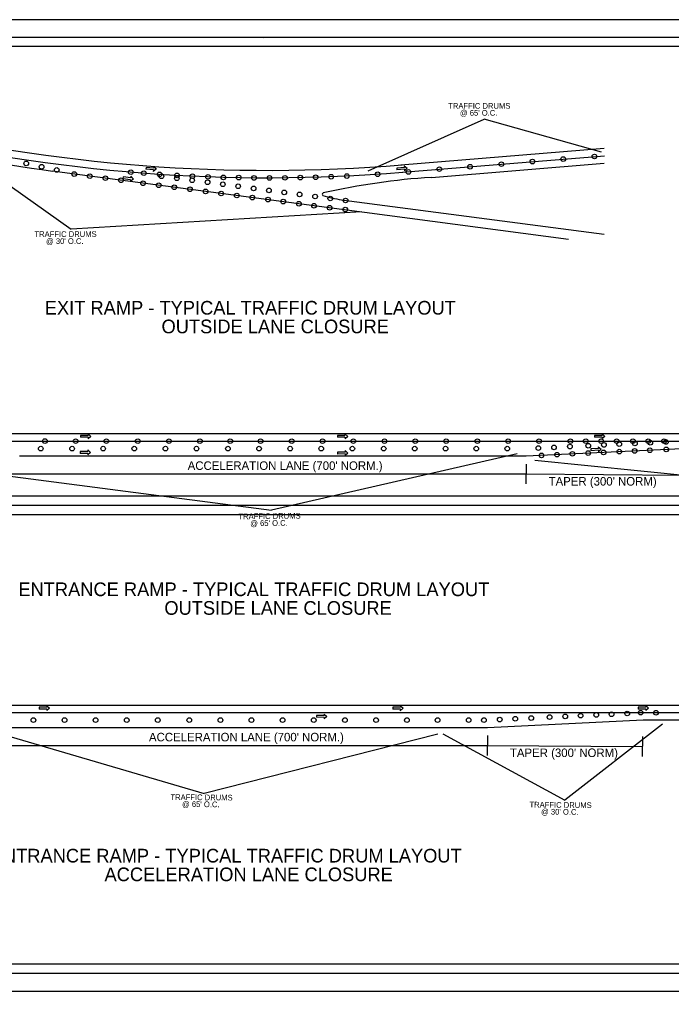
# Model space of a CAD drawing. Extents: x -500 to 213, y 382723 to 382830.
# Drawn here: x -79.9 to -8.3, y 382723.1 to 382829.8 of the extents above; entities that cross this region are included whole.
import ezdxf

# ---------------------------------------------------------------- set-up
doc = ezdxf.new("R2010")
doc.units = 0
for name, color, linetype in [('Default', 7, 'Continuous'), ('R_Border', 7, 'Continuous'), ('R_Border Plan-Plan', 7, 'Continuous'), ('R_MOT', 7, 'Continuous'), ('R_No Plot', 7, 'Continuous')]:
    doc.layers.add(name, color=color, linetype=linetype)

# ---------------------------------------------------------------- blocks, each defined once
blk = doc.blocks.new('DOT')
at = {"layer": 'Default'}
blk.add_circle((-0.4, -0.3), 3.75, dxfattribs=at)
blk = doc.blocks.new('SARROW')
at = {"layer": 'Default'}
for p, q in [((15.6, 3.2), (-13.8, 3.2)), ((-13.8, 3.2), (-13.8, -2.8)), ((15.6, 8.2), (15.6, 3.2)), ((15.6, 8.2), (26, 0.2)), ((26, 0.2), (15.6, -7.8)), ((15.6, -2.8), (-13.8, -2.8)), ((15.6, -2.8), (15.6, -7.8))]:
    blk.add_line(p, q, dxfattribs=at)

msp = doc.modelspace()

# ---------------------------------------------------------------- linework, layer by layer
at = {"layer": 'Default'}
for p, q in [((-38.04, 382813.83), (-15.74, 382815.66)), ((-37.87, 382813.03), (-15.7, 382814.84)), ((-76.32, 382813.17), (-19.64, 382805.7)), ((-34.7, 382812.47), (-15.74, 382814.02)), ((-44.58, 382810.02), (-15.74, 382806.22)), ((-97.81, 382784.35), (6.37, 382784.35)), ((-97.83, 382783.53), (6.35, 382783.53)), ((-24.28, 382781.9), (-7.21, 382782.72)), ((-79.93, 382781.9), (-24.28, 382781.9)), ((-24.29, 382781.01), (-24.34, 382778.83)), ((-89.24, 382779.92), (-24.32, 382779.92)), ((-107.24, 382754.56), (2.89, 382754.56)), ((-107.26, 382753.75), (2.87, 382753.75)), ((-28.53, 382752.11), (-11.45, 382752.93)), ((-11.45, 382752.93), (2.85, 382752.93)), ((-84.18, 382752.11), (-28.53, 382752.11)), ((-28.54, 382751.22), (-28.59, 382749.04)), ((-93.49, 382750.13), (-28.56, 382750.13)), ((-11.51, 382751.1), (-11.57, 382748.92))]:
    msp.add_line(p, q, dxfattribs=at)
for centre, major_axis, start_param, end_param in [((-52.59, 383072.52), (0, 260.09), 2.945637, 3.209664), ((-52.59, 383072.52), (0, 259.28), 2.945637, 3.209664), ((-52.59, 383072.52), (0, 260.91), 2.94688, 3.032274), ((-29.96, 382704.91), (0, 107.71), 0.052832, 0.186328), ((-46.57, 382810.62), (0, 0.136), 0.197268, 2.831699), ((-43.23, 382824.76), (0, -14.83), 6.00653, 6.174382)]:
    msp.add_ellipse(centre, major_axis=major_axis, ratio=0.833333, start_param=start_param, end_param=end_param, dxfattribs=at)
at = {"layer": 'R_Border'}
for p, q in [((-129.35, 382827.85), (28.74, 382827.85)), ((-53.09, 382827.72), (-53.09, 382827.72)), ((-53.09, 382827.72), (-53.09, 382827.72)), ((28.74, 382725.12), (-129.35, 382725.12))]:
    msp.add_line(p, q, dxfattribs=at)
at = {"layer": 'R_Border Plan-Plan'}
msp.add_line((-129.35, 382776.49), (28.74, 382776.49), dxfattribs=at)
at = {"layer": 'R_MOT'}
for p, q in [((-41.65, 382813.18), (-28.92, 382818.85)), ((-16.02, 382815.23), (-28.92, 382818.85)), ((-86.86, 382815.7), (-74.26, 382806.8)), ((-66.44, 382812.77), (-66.48, 382812.74)), ((-42.36, 382808.7), (-74.26, 382806.8)), ((-25.28, 382782.14), (-52.26, 382775.94)), ((-91.94, 382781.1), (-52.26, 382775.94)), ((-23.33, 382781.45), (-3.36, 382779.43)), ((-24.32, 382779.92), (-7.29, 382779.8)), ((-9.32, 382752.47), (-20.05, 382744.12)), ((-82.48, 382751.57), (-59.64, 382744.86)), ((-33.99, 382751.38), (-59.64, 382744.86)), ((-33.46, 382751.4), (-20.05, 382744.12)), ((-28.56, 382750.13), (-11.54, 382750.01))]:
    msp.add_line(p, q, dxfattribs=at)
at = {"layer": 'R_No Plot'}
for points in [[(-135.56, 382829.8), (31.11, 382829.8), (31.11, 382723.13), (-135.56, 382723.13)], [(27.74, 382777.49), (-128.35, 382777.49), (-128.35, 382826.85), (-3.58, 382826.85), (-3.58, 382821.91), (5.19, 382821.91), (17.24, 382821.91), (17.24, 382810.74), (27.74, 382810.74)], [(-128.35, 382826.85), (-3.58, 382826.85), (-3.58, 382821.91), (5.19, 382821.91), (17.24, 382821.91), (17.24, 382810.74), (27.74, 382810.74), (27.74, 382726.12), (-128.35, 382726.12)], [(-128.35, 382775.49), (27.74, 382775.49), (27.74, 382726.12), (-128.35, 382726.12)]]:
    msp.add_lwpolyline(points, close=True, dxfattribs=at)

# ---------------------------------------------------------------- block references
at = {"layer": 'R_MOT', "xscale": 0.06809210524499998, "yscale": 0.06809210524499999}
for p in [(-79.16, 382814.02), (-26.99, 382813.94), (-23.58, 382814.22), (-20.2, 382814.5), (-16.77, 382814.78), (-77.47, 382813.65), (-75.81, 382813.3), (-73.89, 382812.85), (-67.68, 382813.06), (-66.25, 382812.95), (-64.52, 382812.82), (-40.57, 382812.83), (-37.19, 382813.08), (-33.8, 382813.39), (-30.42, 382813.66), (-72.18, 382812.62), (-70.47, 382812.4), (-68.75, 382812.17), (-66.33, 382811.85), (-64.31, 382812.61), (-62.62, 382812.39), (-62.6, 382812.71), (-60.94, 382812.17), (-60.91, 382812.62), (-59.25, 382811.95), (-59.2, 382812.55), (-57.57, 382811.73), (-57.51, 382812.49), (-55.82, 382812.46), (-54.14, 382812.43), (-52.45, 382812.43), (-50.75, 382812.44), (-49.07, 382812.46), (-47.38, 382812.5), (-45.68, 382812.56), (-43.96, 382812.63), (-64.61, 382811.63), (-62.9, 382811.4), (-61.18, 382811.18), (-59.47, 382810.95), (-57.76, 382810.72), (-55.89, 382811.51), (-54.19, 382811.28), (-52.51, 382811.06), (-50.83, 382810.84), (-49.15, 382810.62), (-56.04, 382810.5), (-54.33, 382810.27), (-52.61, 382810.05), (-50.94, 382809.83), (-49.22, 382809.6), (-47.44, 382810.39), (-45.77, 382810.17), (-44.09, 382809.95), (-47.56, 382809.38), (-45.85, 382809.16), (-44.13, 382808.95)]:
    msp.add_blockref('DOT', p, dxfattribs=at)
at = {"layer": 'R_MOT'}
for name, p, xscale, yscale, rotation in [('SARROW', (-65.65, 382813.42), 0.028413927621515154, 0.03399546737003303, -5.657384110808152), ('SARROW', (-38.1, 382813.41), 0.028400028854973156, 0.03401210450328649, 4.632677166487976), ('SARROW', (-68.16, 382812.36), 0.028434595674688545, 0.03397075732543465, -6.906452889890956), ('SARROW', (-72.84, 382784.05), 0.02839678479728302, 0.03401599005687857, -0.3179055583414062), ('SARROW', (-44.63, 382784.04), 0.028403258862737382, 0.03400823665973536, 0.21294869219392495), ('SARROW', (-16.41, 382784.05), 0.028395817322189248, 0.03401714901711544, -0.402879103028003), ('DOT', (-77.11, 382783.55), 0.06809210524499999, 0.06809210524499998, -4.676990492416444), ('DOT', (-73.73, 382783.54), 0.06809210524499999, 0.06809210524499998, -4.676990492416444), ('DOT', (-70.36, 382783.54), 0.06809210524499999, 0.06809210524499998, -4.676990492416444), ('DOT', (-66.91, 382783.54), 0.06809210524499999, 0.06809210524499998, -4.676990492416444), ('DOT', (-63.48, 382783.54), 0.06809210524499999, 0.06809210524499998, -4.676990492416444), ('DOT', (-60.09, 382783.54), 0.06809210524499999, 0.06809210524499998, -4.676990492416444), ('DOT', (-56.76, 382783.54), 0.06809210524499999, 0.06809210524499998, -4.676990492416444), ('DOT', (-53.43, 382783.54), 0.06809210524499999, 0.06809210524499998, -4.676990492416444), ('DOT', (-50.01, 382783.54), 0.06809210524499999, 0.06809210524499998, -4.676990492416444), ('DOT', (-46.62, 382783.54), 0.06809210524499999, 0.06809210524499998, -4.676990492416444), ('DOT', (-43.24, 382783.54), 0.06809210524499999, 0.06809210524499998, -4.676990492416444), ('DOT', (-39.82, 382783.54), 0.06809210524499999, 0.06809210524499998, -4.676990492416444), ('DOT', (-36.44, 382783.54), 0.06809210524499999, 0.06809210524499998, -4.676990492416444), ('DOT', (-33.05, 382783.54), 0.06809210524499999, 0.06809210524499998, -4.676990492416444), ('DOT', (-29.62, 382783.54), 0.06809210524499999, 0.06809210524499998, -4.676990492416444), ('DOT', (-26.24, 382783.54), 0.06809210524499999, 0.06809210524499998, -4.676990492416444), ('DOT', (-22.85, 382783.54), 0.06809210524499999, 0.06809210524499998, -4.676990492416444), ('DOT', (-21.21, 382782.86), 0.06809210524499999, 0.06809210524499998, -4.676990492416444), ('DOT', (-19.46, 382782.95), 0.06809210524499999, 0.06809210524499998, -4.676990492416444), ('DOT', (-19.41, 382783.54), 0.06809210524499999, 0.06809210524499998, -4.676990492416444), ('DOT', (-17.72, 382783.54), 0.06809210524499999, 0.06809210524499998, -4.676990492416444), ('DOT', (-17.45, 382783.04), 0.06809210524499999, 0.06809210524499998, -4.676990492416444), ('DOT', (-16.03, 382783.54), 0.06809210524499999, 0.06809210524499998, -4.676990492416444), ('DOT', (-15.73, 382783.13), 0.06809210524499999, 0.06809210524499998, -4.676990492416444), ('DOT', (-14.33, 382783.54), 0.06809210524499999, 0.06809210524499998, -4.676990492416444), ('DOT', (-14.04, 382783.21), 0.06809210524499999, 0.06809210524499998, -4.676990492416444), ('DOT', (-12.55, 382783.54), 0.06809210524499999, 0.06809210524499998, -4.676990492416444), ('DOT', (-12.32, 382783.29), 0.06809210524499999, 0.06809210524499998, -4.676990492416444), ('DOT', (-10.86, 382783.54), 0.06809210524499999, 0.06809210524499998, -4.676990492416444), ('DOT', (-10.64, 382783.37), 0.06809210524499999, 0.06809210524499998, -4.676990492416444), ('DOT', (-9.13, 382783.54), 0.06809210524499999, 0.06809210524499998, -4.676990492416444), ('DOT', (-8.92, 382783.45), 0.06809210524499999, 0.06809210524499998, -4.676990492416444), ('DOT', (-77.56, 382782.72), 0.06809210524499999, 0.06809210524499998, -4.676990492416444), ('DOT', (-74.12, 382782.72), 0.06809210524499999, 0.06809210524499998, -4.676990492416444), ('SARROW', (-72.88, 382782.28), 0.02839678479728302, 0.03401599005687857, -0.3179055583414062), ('DOT', (-70.71, 382782.72), 0.06809210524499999, 0.06809210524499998, -4.676990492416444), ('DOT', (-67.29, 382782.72), 0.06809210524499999, 0.06809210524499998, -4.676990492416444), ('DOT', (-63.87, 382782.72), 0.06809210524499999, 0.06809210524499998, -4.676990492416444), ('DOT', (-60.46, 382782.72), 0.06809210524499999, 0.06809210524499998, -4.676990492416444), ('DOT', (-57.01, 382782.72), 0.06809210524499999, 0.06809210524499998, -4.676990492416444), ('DOT', (-53.59, 382782.72), 0.06809210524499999, 0.06809210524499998, -4.676990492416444), ('DOT', (-50.18, 382782.72), 0.06809210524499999, 0.06809210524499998, -4.676990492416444), ('DOT', (-46.77, 382782.72), 0.06809210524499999, 0.06809210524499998, -4.676990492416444), ('SARROW', (-44.6, 382782.21), 0.028403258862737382, 0.03400823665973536, 0.21294869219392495), ('DOT', (-43.35, 382782.72), 0.06809210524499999, 0.06809210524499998, -4.676990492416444), ('DOT', (-39.91, 382782.72), 0.06809210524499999, 0.06809210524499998, -4.676990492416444), ('DOT', (-36.5, 382782.72), 0.06809210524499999, 0.06809210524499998, -4.676990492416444), ('DOT', (-33.12, 382782.72), 0.06809210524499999, 0.06809210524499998, -4.676990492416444), ('DOT', (-29.74, 382782.72), 0.06809210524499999, 0.06809210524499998, -4.676990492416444), ('DOT', (-26.34, 382782.72), 0.06809210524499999, 0.06809210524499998, -4.676990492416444), ('DOT', (-22.93, 382782.78), 0.06809210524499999, 0.06809210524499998, -4.676990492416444), ('DOT', (-22.58, 382781.98), 0.06809210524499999, 0.06809210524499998, -4.676990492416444), ('DOT', (-22.58, 382781.98), 0.06809210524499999, 0.06809210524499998, -4.676990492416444), ('DOT', (-20.88, 382782.06), 0.06809210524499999, 0.06809210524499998, -4.676990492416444), ('DOT', (-19.19, 382782.15), 0.06809210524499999, 0.06809210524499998, -4.676990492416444), ('DOT', (-17.46, 382782.23), 0.06809210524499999, 0.06809210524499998, -4.676990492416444), ('SARROW', (-16.8, 382782.59), 0.028461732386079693, 0.03393836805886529, 3.589093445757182), ('DOT', (-15.77, 382782.31), 0.06809210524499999, 0.06809210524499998, -4.676990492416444), ('DOT', (-14.04, 382782.39), 0.06809210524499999, 0.06809210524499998, -4.676990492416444), ('DOT', (-12.36, 382782.47), 0.06809210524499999, 0.06809210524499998, -4.676990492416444), ('DOT', (-10.69, 382782.55), 0.06809210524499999, 0.06809210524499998, -4.676990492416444), ('DOT', (-8.89, 382782.64), 0.06809210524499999, 0.06809210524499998, -4.676990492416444), ('SARROW', (-77.36, 382754.22), 0.028398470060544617, 0.03401397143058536, -0.17370681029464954), ('SARROW', (-38.55, 382754.22), 0.02839135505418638, 0.03402249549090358, -0.8188905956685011), ('SARROW', (-11.59, 382754.22), 0.02841423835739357, 0.03399509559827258, 1.0011972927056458), ('SARROW', (-46.93, 382753.31), 0.02839135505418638, 0.03402249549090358, -0.8188905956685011), ('DOT', (-25.46, 382753.08), 0.06809210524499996, 0.06809210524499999, -4.676990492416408), ('DOT', (-23.71, 382753.16), 0.06809210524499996, 0.06809210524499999, -4.676990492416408), ('DOT', (-21.69, 382753.26), 0.06809210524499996, 0.06809210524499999, -4.676990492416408), ('DOT', (-19.98, 382753.34), 0.06809210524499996, 0.06809210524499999, -4.676990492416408), ('DOT', (-18.29, 382753.42), 0.06809210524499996, 0.06809210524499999, -4.676990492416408), ('DOT', (-16.57, 382753.5), 0.06809210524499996, 0.06809210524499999, -4.676990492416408), ('DOT', (-14.89, 382753.58), 0.06809210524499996, 0.06809210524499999, -4.676990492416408), ('DOT', (-13.17, 382753.66), 0.06809210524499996, 0.06809210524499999, -4.676990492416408), ('DOT', (-11.7, 382753.75), 0.06809210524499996, 0.06809210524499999, -4.676990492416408), ('DOT', (-10.02, 382753.74), 0.06809210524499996, 0.06809210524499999, -4.676990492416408), ('DOT', (-78.37, 382752.93), 0.06809210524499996, 0.06809210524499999, -4.676990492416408), ('DOT', (-74.95, 382752.93), 0.06809210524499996, 0.06809210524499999, -4.676990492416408), ('DOT', (-71.54, 382752.93), 0.06809210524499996, 0.06809210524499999, -4.676990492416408), ('DOT', (-68.12, 382752.93), 0.06809210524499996, 0.06809210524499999, -4.676990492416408), ('DOT', (-64.71, 382752.93), 0.06809210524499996, 0.06809210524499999, -4.676990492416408), ('DOT', (-61.25, 382752.93), 0.06809210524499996, 0.06809210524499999, -4.676990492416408), ('DOT', (-57.83, 382752.93), 0.06809210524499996, 0.06809210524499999, -4.676990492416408), ('DOT', (-54.43, 382752.93), 0.06809210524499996, 0.06809210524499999, -4.676990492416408), ('DOT', (-51.01, 382752.93), 0.06809210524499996, 0.06809210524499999, -4.676990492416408), ('DOT', (-47.59, 382752.93), 0.06809210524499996, 0.06809210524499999, -4.676990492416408), ('DOT', (-44.16, 382752.93), 0.06809210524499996, 0.06809210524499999, -4.676990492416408), ('DOT', (-40.75, 382752.93), 0.06809210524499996, 0.06809210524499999, -4.676990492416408), ('DOT', (-37.36, 382752.93), 0.06809210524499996, 0.06809210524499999, -4.676990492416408), ('DOT', (-33.99, 382752.93), 0.06809210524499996, 0.06809210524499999, -4.676990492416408), ('DOT', (-30.58, 382752.93), 0.06809210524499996, 0.06809210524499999, -4.676990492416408), ('DOT', (-28.9, 382752.93), 0.06809210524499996, 0.06809210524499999, -4.676990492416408), ('DOT', (-27.17, 382752.99), 0.06809210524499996, 0.06809210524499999, -4.676990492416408)]:
    msp.add_blockref(name, p, dxfattribs=dict(at, xscale=xscale, yscale=yscale, rotation=rotation))

# ---------------------------------------------------------------- texts
at = {"layer": 'Default'}
for s, rotation, p in [("ACCELERATION LANE (700' NORM.)", 0.0037, (-61.46, 382780.37)), ("TAPER (300' NORM)", 0.0038, (-21.83, 382778.65)), ("ACCELERATION LANE (700' NORM.)", 0.0037, (-65.71, 382750.58)), ("TAPER (300' NORM)", 0.0038, (-26.08, 382748.86))]:
    msp.add_text(s, height=0.9368, rotation=rotation, dxfattribs=at).set_placement(p)
at = {"layer": 'R_MOT'}
for s, height, p in [('TRAFFIC DRUMS ', 0.625, (-32.85, 382820)), ("@ 65' O.C.", 0.625, (-31.57, 382819.24)), ('TRAFFIC DRUMS ', 0.625, (-78.28, 382805.93)), ("@ 30' O.C.", 0.625, (-77.01, 382805.16)), ('EXIT RAMP - TYPICAL TRAFFIC DRUM LAYOUT', 1.5, (-77.15, 382797.41)), ('OUTSIDE LANE CLOSURE', 1.5, (-64.33, 382795.36)), ('ENTRANCE RAMP - TYPICAL TRAFFIC DRUM LAYOUT', 1.5, (-80.05, 382766.52)), ('OUTSIDE LANE CLOSURE', 1.5, (-64.02, 382764.47)), ('ENTRANCE RAMP - TYPICAL TRAFFIC DRUM LAYOUT', 1.5, (-83.08, 382737.29)), ('ACCELERATION LANE CLOSURE', 1.5, (-70.59, 382735.24))]:
    msp.add_text(s, height=height, dxfattribs=at).set_placement(p)
for s, rotation, p in [('TRAFFIC DRUMS ', 0.6305, (-55.88, 382774.95)), ("@ 65' O.C.", 0.6305, (-54.59, 382774.2)), ('TRAFFIC DRUMS ', 359.4579, (-63.35, 382744.16)), ("@ 65' O.C.", 359.4579, (-62.08, 382743.39)), ('TRAFFIC DRUMS ', 359.4579, (-23.93, 382743.33)), ("@ 30' O.C.", 359.4579, (-22.66, 382742.56))]:
    msp.add_text(s, height=0.625, rotation=rotation, dxfattribs=at).set_placement(p)

doc.saveas('drawing.dxf')
